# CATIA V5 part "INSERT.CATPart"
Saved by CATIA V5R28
Part number: INSERT
Revision: ---
Publications: "MasterKeywayAxis", "InsertFrontFace", "InsertRearFace", "Logical Termination.1", "Logical Pin.1", "CaCP", "Face_generated(CaCP)", "Axis_generated(CaCP)", "Face_generated(CaCP).1", "BaCP", "Face_generated(BaCP)", "Axis_generated(BaCP)", "Face_generated(BaCP).1", "CCP", "Face_generated(CCP)", "Axis_generated(CCP)", "Face_generated(CCP).1", "BCP", "BCPRPoint_generated(BCP)", "BCPPlane_generated(BCP)"
Bounding box of the stored display mesh (mm): x 0 to 28.397, y -13.5 to 13.5, z -6.274 to 6.02
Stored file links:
  C:\Users\ajc8720\Documents\BOEING_WORK\0001-2CES\004-AP242\Boeing-Generic_Harness_R3\INSERT.CATPart
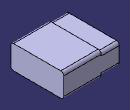
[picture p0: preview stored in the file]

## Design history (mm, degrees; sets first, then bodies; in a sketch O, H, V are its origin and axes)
Parameters
  PartNumber = "INSERT"
AxisSystem1 "MasterKeywayAxis": origin (0, 0, 0), X (1, 0, 0), Y (0, 1, 0), Z (0, 0, 1)
Set1 "EGF"
  Set2 "CaCPOBody"
    Point1 "CaCPPoint": (9.271, 0, 0)
  Set3 "BCPOBody"
    Plane1 "BCPPlane_Original": type Offset, RefPlane yz-plane, Offset 28.3972
    Point2 "BCPRPoint": (28.3972, 0, 0)
    Line1: type PtDir, RefPoint Point2, Direction (0, 1, 0), Start 0, End 2.54
    Plane2 "BCPPlane": type Angle, RefPlane yz-plane, Direction Line1, Angle 180
  Set4 "CCPOBody"
    Point3 "CCPRPoint": (-0.2032, 0, 0)
    Plane3 "CCPPlane": type OffsetPt, RefPlane yz-plane, RefPoint Point3
  Set5 "BaCPOBody"
    Point4 "BaCPRPoint": (21.8694, 0, 0)
    Plane4 "BaCPCPlane": type OffsetPt, RefPlane yz-plane, RefPoint Point4
Body1 "Insert" (main body)
  Sketch1 on yz-plane, origin (0, 0, 0), H (0, 1, 0), V (0, 0, 1)
    line L1 (-13.5001, 5.2197) -> (13.5001, 5.2197)
    line L2 (13.5001, 5.2197) -> (13.5001, -5.2197)
    line L3 (13.5001, -5.2197) -> (-13.5001, -5.2197)
    line L4 (-13.5001, -5.2197) -> (-13.5001, 5.2197)
    length L1 = 27.0002
    distance L3 L1 = 10.4394
    horizontal: L1 H, L3 H
    vertical: L2 V, L4 V
    symmetry: L2 L4 V, L3 L1 H
  Pad1 "Front": profile Sketch1, direction (1, 0, 0), length 9.271
  Fillet1: radius 1.4986, on edge [face of Pad1 | face of Pad1] (x4)
  Sketch2 on yz-plane, origin (0, 0, 0), H (0, 1, 0), V (0, 0, 1)
    line L1 (-13.5001, 6.0198) -> (13.5001, 6.0198)
    line L2 (13.5001, 6.0198) -> (13.5001, -6.0198)
    line L3 (13.5001, -6.0198) -> (-13.5001, -6.0198)
    line L4 (-13.5001, -6.0198) -> (-13.5001, 6.0198)
    length L1 = 27.0002
    length L2 = 12.0396
    horizontal: L1 H, L3 H
    vertical: L2 V, L4 V
    symmetry: L4 L2 V, L3 L1 H
  Pad2 "Back": profile Sketch2, direction (1, 0, 0), length 28.3972, opposite side length -9.271
  Fillet2: radius 1.4986, on 4 edges
  Sketch3 on yz-plane, origin (0, 0, 0), H (0, 1, 0), V (0, 0, 1)
    arc A1 centre (0, -3.7846) radius 2.4892 from (-2.4892, -3.7846) to (2.4892, -3.7846) ccw
    point P1 (0, -3.7846)
    line L1 (-2.4892, -3.7846) -> (2.4892, -3.7846)
    radius A1 = 2.4892
    distance A1 H = 6.2738
    coincidence: P1 V, L1 P1
    horizontal: L1 H
  Pad3 "Key": profile Sketch3, direction (1, 0, 0), length 10.287, opposite side length -7.7724
Body2 "CaCP"
  Sketch4 on start face of Pad2, origin (9.271, 0, 0), H (0, 1, 0), V (0, 0, 1)
    arc A1 centre (0, 0) radius 1.016 from (-0.672, 0.762) to (0.672, 0.762) ccw
    line L1 (-0.672, 0.762) -> (0.672, 0.762)
    distance L1 H = 0.762
    radius A1 = 1.016
  Pad4: profile Sketch4, direction (1, 0, 0), length 0.508
Body3 "BaCP"
  Sketch5 on Plane4, origin (21.8694, 0, 0), H (0, 1, 0), V (0, 0, 1)
    arc A1 centre (0, 0) radius 1.016 from (-0.672, 0.762) to (0.672, 0.762) ccw
    line L1 (-0.672, 0.762) -> (0.672, 0.762)
    distance L1 H = 0.762
    radius A1 = 1.016
  Sketch6 on Plane4, origin (21.8694, 0, 0), H (0, 1, 0), V (0, 0, 1)
    circle A1 centre (0, 0) radius 1.27
    radius A1 = 1.27
  Pad5: profile Sketch6, direction (1, 0, 0), length 0.254, opposite side length 0.254
  Pocket1: profile Sketch5, direction (1, 0, 0), through (limit type 6)
Body4 "CCP"
  Sketch7 on Plane3, origin (-0.2032, 0, 0), H (0, 1, 0), V (0, 0, 1)
    arc A1 centre (0, 0) radius 1.016 from (-0.672, 0.762) to (0.672, 0.762) ccw
    line L1 (-0.672, 0.762) -> (0.672, 0.762)
    distance L1 H = 0.762
    radius A1 = 1.016
  Sketch8 on Plane3, origin (-0.2032, 0, 0), H (0, 1, 0), V (0, 0, 1)
    circle A1 centre (0, 0) radius 1.27
    radius A1 = 1.27
  Pad6: profile Sketch8, direction (1, 0, 0), length 0.254, opposite side length 0.254
  Pocket2: profile Sketch7, direction (-1, 0, 0), through (limit type 6)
